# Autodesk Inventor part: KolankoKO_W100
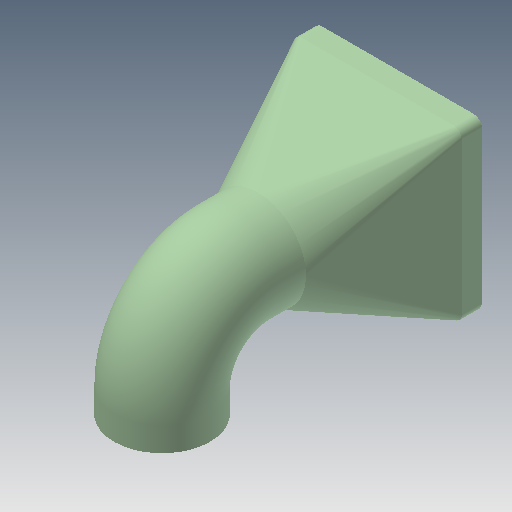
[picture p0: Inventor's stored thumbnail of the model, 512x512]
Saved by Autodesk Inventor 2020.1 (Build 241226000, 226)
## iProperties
Created: 2005-10
Part Number: KolankoKO_W100
Document SubType Name: Modeling
Designer: F.Stasiak
Density: 1 g/cm^3
Material: Ogólny
Appearance: Zielony pastelowy
Manager: www.cadconsulting.pl
Company: Fabian Stasiak CAD Consulting
Author: F.Stasiak
Subject: Zbiór ćwiczeń. Autodesk Inventor 2020. Kurs podstawowy
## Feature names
1. Wyciągnięcie proste1 [Extrusion]
2. Wyciągnięcie złożone2
3. Przeciągnięcie1
4. Skorupa2
## Parameters: d0 = 2 mm, d1 = 25 mm, d2 = 0, d32 = 0, d33 = 90 deg, d34 = 0, d35 = 90 deg, d42 = 0, d44 = 0, d45 = 2 mm, d46 = 0
